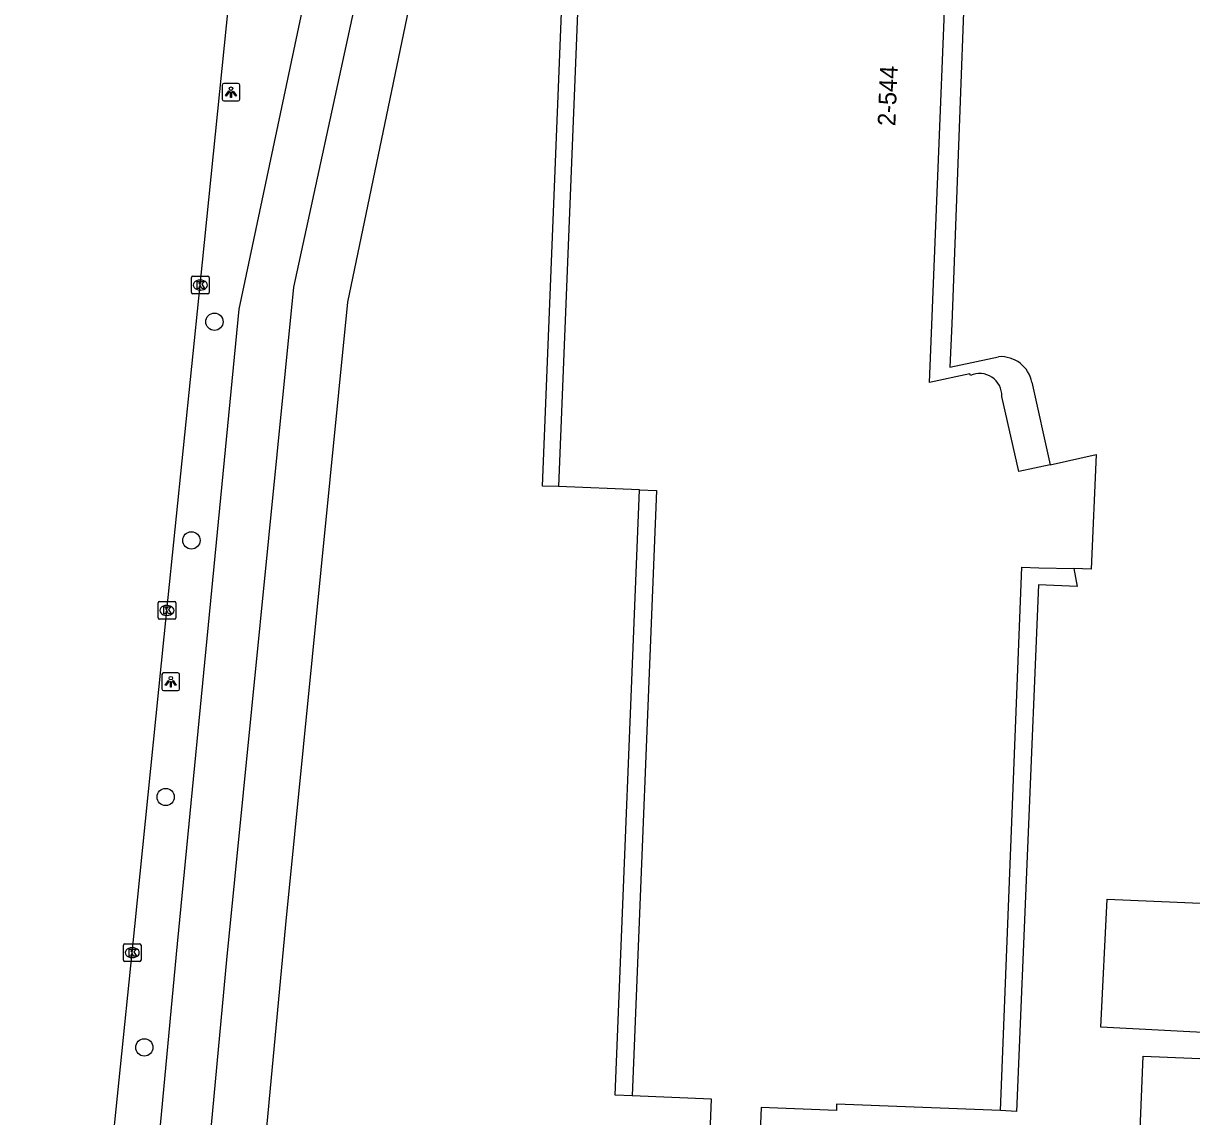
# Model space of a CAD drawing. Extents: x 161355 to 162026, y 386504 to 387459.
# Drawn here: x 161356.8 to 161423, y 386577.7 to 386639.6 of the extents above; entities that cross this region are included whole.
import ezdxf

# ---------------------------------------------------------------- set-up
doc = ezdxf.new("R2010")
doc.units = 0
for name, color, linetype in [('IMGEO_Boom', 7, 'Continuous'), ('IMGEO_Fietspad_open', 7, 'Continuous'), ('IMGEO_Kolk', 7, 'Continuous'), ('IMGEO_Lichtpunt', 7, 'Continuous'), ('IMGEO_Pand', 7, 'Continuous'), ('IMGEO_Pand_nummerreeks', 7, 'Continuous'), ('IMGEO_Pand_vergunning_verleend', 7, 'Continuous'), ('IMGEO_Rijbaan_lokaal_gesloten', 7, 'Continuous'), ('IMGEO_Voetpad_open', 7, 'Continuous')]:
    doc.layers.add(name, color=color, linetype=linetype)

msp = doc.modelspace()

# ---------------------------------------------------------------- linework, layer by layer
at = {"layer": 'IMGEO_Boom'}
for centre in [(161367.658, 386622.716), (161366.353, 386610.342), (161364.898, 386595.817), (161363.689, 386581.642)]:
    msp.add_circle(centre, 0.489, dxfattribs=at)
at = {"layer": 'IMGEO_Fietspad_open'}
for points in [[(161361.751, 386546.816), (161365.503, 386586.919), (161369.056, 386623.43), (161372.78, 386641.005), (161373.235, 386643.851), (161373.548, 386646.346), (161375.763, 386665.263), (161375.91, 386666.917), (161376.529, 386689.717), (161378.997, 386712.85)], [(161381.864, 386712.557), (161379.47, 386690.727), (161378.77, 386666.617), (161375.998, 386642.707), (161375.624, 386640.752), (161372.137, 386624.68), (161368.347, 386586.608), (161364.46, 386544.778), (161364.392, 386543.778), (161364.303, 386538.723), (161364.292, 386538.52), (161364.3, 386538.317), (161364.326, 386538.115), (161364.37, 386537.917)]]:
    msp.add_lwpolyline(points, dxfattribs=at)
at = {"layer": 'IMGEO_Kolk'}
for p, q in [((161366.356, 386624.367), (161366.356, 386625.219)), ((161366.431, 386625.293), (161367.283, 386625.293)), ((161366.844, 386625.073), (161366.869, 386625.073)), ((161367.357, 386625.219), (161367.357, 386624.367)), ((161367.283, 386624.293), (161366.431, 386624.293)), ((161366.867, 386624.513), (161366.842, 386624.513)), ((161364.467, 386605.95), (161364.467, 386606.802)), ((161364.542, 386606.876), (161365.394, 386606.876)), ((161364.955, 386606.656), (161364.98, 386606.656)), ((161365.468, 386606.802), (161365.468, 386605.95)), ((161365.394, 386605.876), (161364.542, 386605.876)), ((161364.978, 386606.096), (161364.953, 386606.096)), ((161362.503, 386586.577), (161362.503, 386587.429)), ((161362.578, 386587.503), (161363.43, 386587.503)), ((161362.991, 386587.283), (161363.016, 386587.283)), ((161363.504, 386587.429), (161363.504, 386586.577)), ((161363.43, 386586.503), (161362.578, 386586.503)), ((161363.014, 386586.723), (161362.989, 386586.723))]:
    msp.add_line(p, q, dxfattribs=at)
for points in [[(161366.356, 386624.367), (161366.356, 386625.219)], [(161366.431, 386625.293), (161367.283, 386625.293)], [(161366.677, 386624.993), (161366.8, 386624.993), (161366.8, 386624.842), (161366.93, 386624.993), (161367.094, 386624.993), (161366.948, 386624.842), (161367.101, 386624.593), (161366.949, 386624.593), (161366.864, 386624.757), (161366.8, 386624.69), (161366.8, 386624.593), (161366.677, 386624.593), (161366.677, 386624.993)], [(161367.357, 386625.219), (161367.357, 386624.367)], [(161367.283, 386624.293), (161366.431, 386624.293)], [(161364.467, 386605.95), (161364.467, 386606.802)], [(161364.542, 386606.876), (161365.394, 386606.876)], [(161364.788, 386606.576), (161364.911, 386606.576), (161364.911, 386606.425), (161365.041, 386606.576), (161365.205, 386606.576), (161365.059, 386606.425), (161365.212, 386606.176), (161365.06, 386606.176), (161364.975, 386606.34), (161364.911, 386606.273), (161364.911, 386606.176), (161364.788, 386606.176), (161364.788, 386606.576)], [(161365.468, 386606.802), (161365.468, 386605.95)], [(161365.394, 386605.876), (161364.542, 386605.876)], [(161362.503, 386586.577), (161362.503, 386587.429)], [(161362.578, 386587.503), (161363.43, 386587.503)], [(161362.824, 386587.203), (161362.947, 386587.203), (161362.947, 386587.052), (161363.077, 386587.203), (161363.241, 386587.203), (161363.095, 386587.052), (161363.248, 386586.803), (161363.096, 386586.803), (161363.011, 386586.967), (161362.947, 386586.9), (161362.947, 386586.803), (161362.824, 386586.803), (161362.824, 386587.203)], [(161363.504, 386587.429), (161363.504, 386586.577)], [(161363.43, 386586.503), (161362.578, 386586.503)]]:
    msp.add_lwpolyline(points, dxfattribs=at)
for centre, start, end in [((161366.433, 386625.217), 91.55205, 178.44795), ((161366.433, 386625.217), 91.55205, 178.44795), ((161367.281, 386625.217), 1.55205, 88.44795), ((161367.281, 386625.217), 1.55205, 88.44795), ((161366.433, 386624.369), 181.55205, 268.44795), ((161366.433, 386624.369), 181.55205, 268.44795), ((161367.281, 386624.369), 271.55205, 358.44795), ((161367.281, 386624.369), 271.55205, 358.44795), ((161364.544, 386606.8), 91.55205, 178.44795), ((161364.544, 386606.8), 91.55205, 178.44795), ((161365.392, 386606.8), 1.55205, 88.44795), ((161365.392, 386606.8), 1.55205, 88.44795), ((161364.544, 386605.952), 181.55205, 268.44795), ((161364.544, 386605.952), 181.55205, 268.44795), ((161365.392, 386605.952), 271.55205, 358.44795), ((161365.392, 386605.952), 271.55205, 358.44795), ((161362.58, 386587.427), 91.55205, 178.44795), ((161362.58, 386587.427), 91.55205, 178.44795), ((161363.428, 386587.427), 1.55205, 88.44795), ((161363.428, 386587.427), 1.55205, 88.44795), ((161362.58, 386586.579), 181.55205, 268.44795), ((161362.58, 386586.579), 181.55205, 268.44795), ((161363.428, 386586.579), 271.55205, 358.44795), ((161363.428, 386586.579), 271.55205, 358.44795)]:
    msp.add_arc(centre, 0.0765, start, end, dxfattribs=at)
for centre, major_axis, ratio, start_param, end_param in [((161366.843, 386624.793), (-0.387, 0.002), 0.722429, 4.712389, 7.853982), ((161366.868, 386624.793), (-0.39, 0.002), 0.717154, 1.570796, 4.712389), ((161364.954, 386606.376), (-0.387, 0.002), 0.722429, 4.712389, 7.853982), ((161364.979, 386606.376), (-0.39, 0.002), 0.717154, 1.570796, 4.712389), ((161362.99, 386587.003), (-0.387, 0.002), 0.722429, 4.712389, 7.853982), ((161363.015, 386587.003), (-0.39, 0.002), 0.717154, 1.570796, 4.712389)]:
    msp.add_ellipse(centre, major_axis=major_axis, ratio=ratio, start_param=start_param, end_param=end_param, dxfattribs=at)
at = {"layer": 'IMGEO_Lichtpunt'}
for p, q in [((161368.096, 386636.114), (161368.096, 386635.307)), ((161368.096, 386636.114), (161368.096, 386635.307)), ((161368.998, 386636.209), (161368.19, 386636.209)), ((161368.998, 386636.209), (161368.19, 386636.209)), ((161369.092, 386635.307), (161369.092, 386636.114)), ((161369.092, 386635.307), (161369.092, 386636.114)), ((161368.19, 386635.213), (161368.998, 386635.213)), ((161368.19, 386635.213), (161368.998, 386635.213)), ((161364.689, 386602.746), (161364.689, 386601.939)), ((161364.689, 386602.746), (161364.689, 386601.939)), ((161365.591, 386602.841), (161364.783, 386602.841)), ((161365.591, 386602.841), (161364.783, 386602.841)), ((161365.685, 386601.939), (161365.685, 386602.746)), ((161365.685, 386601.939), (161365.685, 386602.746)), ((161364.783, 386601.845), (161365.591, 386601.845)), ((161364.783, 386601.845), (161365.591, 386601.845))]:
    msp.add_line(p, q, dxfattribs=at)
for points in [[(161368.47, 386635.778), (161368.509, 386635.75), (161368.321, 386635.488), (161368.283, 386635.515), (161368.47, 386635.778)], [(161368.572, 386635.73), (161368.619, 386635.73), (161368.619, 386635.408), (161368.572, 386635.408), (161368.572, 386635.73)], [(161368.682, 386635.75), (161368.72, 386635.777), (161368.907, 386635.515), (161368.868, 386635.487), (161368.682, 386635.75)], [(161365.063, 386602.41), (161365.102, 386602.382), (161364.914, 386602.12), (161364.876, 386602.147), (161365.063, 386602.41)], [(161365.165, 386602.362), (161365.212, 386602.362), (161365.212, 386602.04), (161365.165, 386602.04), (161365.165, 386602.362)], [(161365.275, 386602.382), (161365.313, 386602.409), (161365.5, 386602.147), (161365.461, 386602.119), (161365.275, 386602.382)]]:
    msp.add_lwpolyline(points, dxfattribs=at)
for centre in [(161368.595, 386635.912), (161365.188, 386602.544)]:
    msp.add_circle(centre, 0.0994, dxfattribs=at)
for centre, start, end in [((161368.19, 386636.114), 90, 180), ((161368.19, 386636.114), 90, 180), ((161368.998, 386636.114), 0, 90), ((161368.998, 386636.114), 0, 90), ((161368.19, 386635.307), 180, 270), ((161368.19, 386635.307), 180, 270), ((161368.998, 386635.307), 270, 0), ((161368.998, 386635.307), 270, 360), ((161364.783, 386602.746), 90, 180), ((161364.783, 386602.746), 90, 180), ((161365.591, 386602.746), 0, 90), ((161365.591, 386602.746), 0, 90), ((161364.783, 386601.939), 180, 270), ((161364.783, 386601.939), 180, 270), ((161365.591, 386601.939), 270, 0), ((161365.591, 386601.939), 270, 360)]:
    msp.add_arc(centre, 0.0946, start, end, dxfattribs=at)
at = {"layer": 'IMGEO_Pand'}
for points in [[(161389.052, 386661.366), (161387.123, 386613.385)], [(161410.439, 386619.665), (161410.406, 386619.764), (161408.124, 386619.286), (161409.496, 386653.414), (161410.533, 386653.372)], [(161414.949, 386614.624), (161413.178, 386614.235), (161412.209, 386618.494)], [(161414.949, 386614.624), (161417.546, 386615.212), (161417.26, 386608.709), (161416.279, 386608.742)], [(161391.709, 386613.201), (161387.123, 386613.385)], [(161391.709, 386613.201), (161392.668, 386613.162), (161391.29, 386578.895)], [(161412.137, 386578.072), (161413.089, 386602.081), (161413.34, 386608.823), (161414.309, 386608.787), (161416.279, 386608.742)], [(161395.387, 386568.79), (161395.786, 386578.714), (161391.29, 386578.895)], [(161412.137, 386578.072), (161402.865, 386578.43), (161402.85, 386578.064), (161398.585, 386578.236), (161398.193, 386568.482)]]:
    msp.add_lwpolyline(points, dxfattribs=at)
msp.add_arc((161410.97, 386618.545), 1.24, 357.65154, 115.37266, dxfattribs=at)
at = {"layer": 'IMGEO_Pand_vergunning_verleend'}
msp.add_lwpolyline([(161417.808, 386582.78), (161418.178, 386590.027), (161434.891, 386589.315), (161434.754, 386581.904), (161417.808, 386582.78)], dxfattribs=at)
at = {"layer": 'IMGEO_Rijbaan_lokaal_gesloten'}
msp.add_lwpolyline([(161356.845, 386526.767), (161356.983, 386528.182), (161357.055, 386528.822), (161359.038, 386548.229), (161361.03, 386567.642), (161363.004, 386587.003), (161364.968, 386606.376), (161366.857, 386624.793), (161368.724, 386643.195), (161370.724, 386662.56), (161372.926, 386683.94), (161373.851, 386693.007)], dxfattribs=at)
at = {"layer": 'IMGEO_Voetpad_open'}
for points in [[(161367.486, 386541.922), (161367.56, 386544.47), (161371.689, 386588.597), (161375.198, 386623.821), (161379.125, 386642.696), (161381.851, 386666.399), (161382.089, 386671.71), (161382.577, 386690.493), (161385.54, 386717.26), (161385.998, 386721.373), (161387.944, 386738.872)], [(161387.123, 386613.385), (161386.228, 386613.419), (161388.149, 386661.399), (161389.052, 386661.366)], [(161410.533, 386653.372), (161409.388, 386622.596), (161409.271, 386620.154), (161412.023, 386620.738)], [(161413.919, 386619.291), (161414.949, 386614.624)], [(161391.29, 386578.895), (161390.331, 386578.937), (161391.709, 386613.201)], [(161416.279, 386608.742), (161416.467, 386607.728), (161414.293, 386607.834), (161413.038, 386578.017), (161412.137, 386578.072)], [(161418.541, 386540.389), (161418.55, 386540.528), (161420.217, 386581.152), (161436.711, 386580.469)]]:
    msp.add_lwpolyline(points, dxfattribs=at)
msp.add_arc((161412.14, 386618.925), 1.817, 11.62052, 93.67878, dxfattribs=at)

# ---------------------------------------------------------------- texts
at = {"layer": 'IMGEO_Pand_nummerreeks'}
msp.add_text('2-544', height=1, rotation=87.69692, dxfattribs=at).set_placement((161406.184, 386633.776))

doc.saveas('drawing.dxf')
